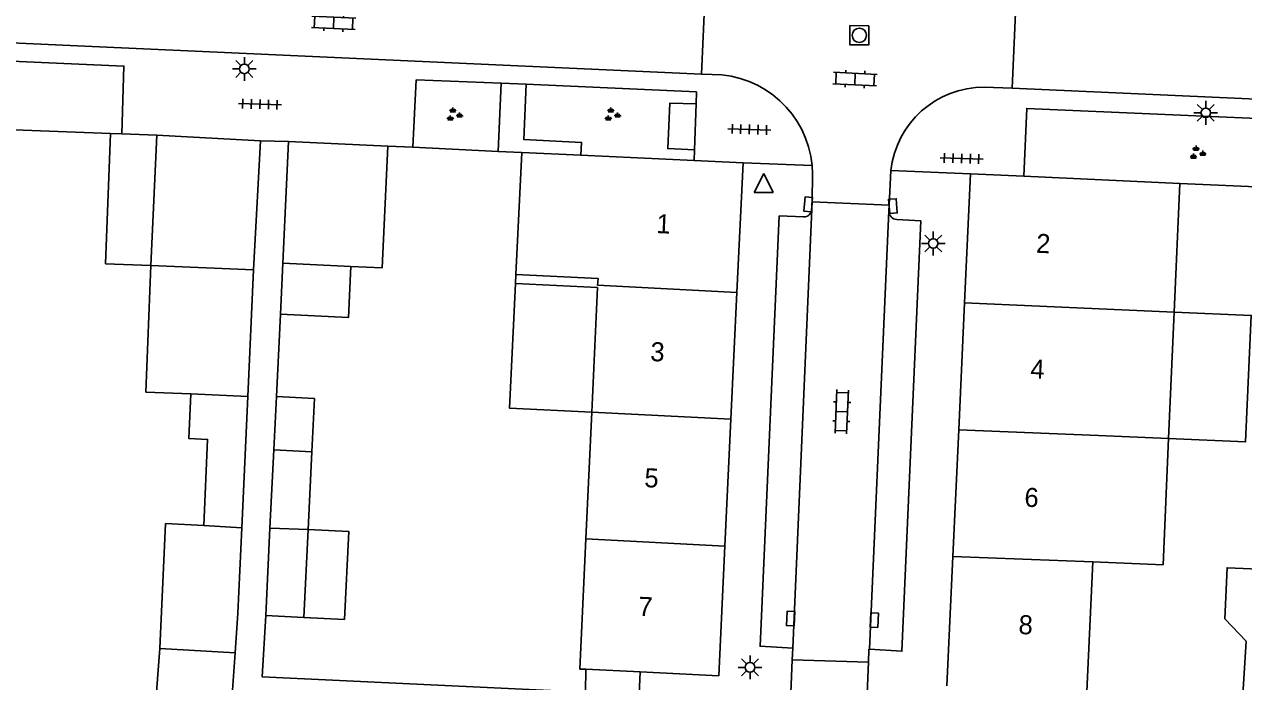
# Model space of a CAD drawing. Extents: x 132994 to 136000, y 393499 to 395512.
# Drawn here: x 133239.8 to 133303.8, y 395304.5 to 395339 of the extents above; entities that cross this region are included whole.
import ezdxf

# ---------------------------------------------------------------- set-up
doc = ezdxf.new("R2010")
doc.units = 0
for name, color, linetype in [('gg-afsc-erfafscheiding', 7, 'Continuous'), ('gg-afsc-muur', 7, 'Continuous'), ('gg-anno-huisnummerreeks BGT', 7, 'Continuous'), ('gg-bbg-bijgebouw', 7, 'Continuous'), ('gg-bbg-gedigitaliseerde bebouwing', 7, 'Continuous'), ('gg-bbg-gedigitaliseerde bijgebouw', 7, 'Continuous'), ('gg-bbg-hoofdgebouw', 7, 'Continuous'), ('gg-bbg-luifel en loopbrug', 7, 'Continuous'), ('gg-bbg-tussenscheiding', 7, 'Continuous'), ('gg-knt-verharding', 7, 'Continuous'), ('gg-knt-verharding nz', 7, 'Continuous'), ('gt-grn-weggrens', 7, 'Continuous'), ('gt-symb-groenvak', 7, 'Continuous'), ('gt-symb-klinker verharding', 7, 'Continuous'), ('gt-symb-kolk', 7, 'Continuous'), ('gt-symb-lichtmast', 7, 'Continuous'), ('gt-symb-rioolschacht', 7, 'Continuous'), ('gt-symb-tegel verharding', 7, 'Continuous'), ('gt-symb-waterafsluiter', 7, 'Continuous')]:
    doc.layers.add(name, color=color, linetype=linetype)

# ---------------------------------------------------------------- blocks, each defined once
blk = doc.blocks.new('gt0-LMAST')
at = {"layer": 'gt-symb-lichtmast'}
for p, q in [((-0.182, 0.173), (-0.447, 0.438)), ((-0.005, 0.246), (-0.005, 0.621)), ((0.172, 0.173), (0.437, 0.438)), ((-0.255, -0.004), (-0.63, -0.004)), ((-0.182, -0.181), (-0.447, -0.446)), ((-0.005, -0.254), (-0.005, -0.629)), ((0.437, -0.446), (0.172, -0.181)), ((0.245, -0.004), (0.62, -0.004))]:
    blk.add_line(p, q, dxfattribs=at)
blk.add_circle((-0.005, -0.004), 0.25, dxfattribs=at)
blk = doc.blocks.new('gt0-KL1')
at = {"layer": 'gt-symb-klinker verharding'}
for p, q in [((-1.15, 0.3), (1.15, 0.3)), ((-1, -0.3), (-1, 0.3)), ((-0.5, 0.3), (-0.5, 0.45)), ((0, -0.3), (0, 0.3)), ((0.5, 0.3), (0.5, 0.45)), ((1, -0.3), (1, 0.3)), ((-1.15, -0.3), (1.15, -0.3)), ((-0.5, -0.45), (-0.5, -0.3)), ((0.5, -0.45), (0.5, -0.3))]:
    blk.add_line(p, q, dxfattribs=at)
blk = doc.blocks.new('gt0-RS')
at = {"layer": 'gt-symb-rioolschacht'}
blk.add_lwpolyline([(-0.5, -0.5), (0.5, -0.5), (0.5, 0.5), (-0.5, 0.5)], close=True, dxfattribs=at)
blk.add_circle((0, 0), 0.375, dxfattribs=at)
blk = doc.blocks.new('gt0-GRVAK')
at = {"layer": 'gt-symb-groenvak'}
for p, q in [((-0.11, 0.189), (-0.228, 0.24)), ((-0.182, 0.153), (0.088, 0.153)), ((-0.091, 0.211), (-0.156, 0.322)), ((-0.047, 0.214), (-0.047, 0.393)), ((-0.004, 0.211), (0.061, 0.322)), ((0.015, 0.189), (0.133, 0.24)), ((0.262, -0.052), (0.197, 0.059)), ((0.305, -0.049), (0.305, 0.13)), ((0.349, -0.052), (0.414, 0.059)), ((-0.245, -0.228), (-0.363, -0.177)), ((-0.318, -0.264), (-0.047, -0.264)), ((-0.226, -0.206), (-0.291, -0.095)), ((-0.183, -0.203), (-0.183, -0.024)), ((-0.139, -0.206), (-0.074, -0.095)), ((-0.12, -0.228), (-0.002, -0.177)), ((0.243, -0.074), (0.125, -0.023)), ((0.17, -0.11), (0.441, -0.11)), ((0.368, -0.074), (0.486, -0.023))]:
    blk.add_line(p, q, dxfattribs=at)
blk = doc.blocks.new('gt0-TEG1')
at = {"layer": 'gt-symb-tegel verharding'}
for p, q in [((-1.125, 0), (1.125, 0)), ((-0.9, -0.25), (-0.9, 0.25)), ((-0.45, -0.25), (-0.45, 0.25)), ((0, -0.25), (0, 0.25)), ((0.45, -0.25), (0.45, 0.25)), ((0.9, -0.25), (0.9, 0.25))]:
    blk.add_line(p, q, dxfattribs=at)
blk = doc.blocks.new('gt0-KOLK')
at = {"layer": 'gt-symb-kolk'}
blk.add_lwpolyline([(0, 0), (0.375, 0), (0.375, 0.4), (-0.375, 0.4), (-0.375, 0), (0, 0)], dxfattribs=at)
blk = doc.blocks.new('gt0-WAFSL')
at = {"layer": 'gt-symb-waterafsluiter'}
for p, q in [((-0.5, -0.333), (0, 0.667)), ((0, 0.667), (0.5, -0.333)), ((0.5, -0.333), (-0.5, -0.333))]:
    blk.add_line(p, q, dxfattribs=at)

msp = doc.modelspace()

# ---------------------------------------------------------------- linework, layer by layer
at = {"layer": 'gg-afsc-erfafscheiding'}
for p, q in [((133253.018, 395319.465), (133253.229, 395323.795)), ((133252.268, 395304.753), (133252.458, 395307.972))]:
    msp.add_line(p, q, dxfattribs=at)
at = {"layer": 'gg-afsc-muur'}
for p, q in [((133238.29, 395333.515), (133244.32, 395333.283)), ((133260.176, 395332.557), (133258.871, 395332.619)), ((133264.663, 395332.346), (133260.176, 395332.557)), ((133265.893, 395332.288), (133264.663, 395332.346)), ((133300.438, 395330.663), (133306.752, 395330.372))]:
    msp.add_line(p, q, dxfattribs=at)
msp.add_lwpolyline([(133252.268, 395304.753), (133269.233, 395303.953), (133269.259, 395305.149)], dxfattribs=at)
at = {"layer": 'gg-bbg-bijgebouw'}
for p, q in [((133246.754, 395333.19), (133252.187, 395332.9)), ((133251.822, 395326.119), (133252.187, 395332.9)), ((133253.356, 395326.479), (133253.657, 395332.865)), ((133253.657, 395332.865), (133258.871, 395332.619)), ((133253.356, 395326.479), (133253.229, 395323.795))]:
    msp.add_line(p, q, dxfattribs=at)
at = {"layer": 'gg-bbg-gedigitaliseerde bebouwing'}
for p, q in [((133265.893, 395332.288), (133265.591, 395325.885)), ((133300.438, 395330.663), (133300.135, 395323.91)), ((133265.568, 395325.399), (133265.591, 395325.885)), ((133269.875, 395325.195), (133265.568, 395325.399)), ((133269.875, 395325.195), (133269.569, 395318.656)), ((133300.135, 395323.91), (133299.838, 395317.273)), ((133269.569, 395318.656), (133269.257, 395311.998)), ((133299.838, 395317.273), (133299.549, 395310.626)), ((133269.257, 395311.998), (133268.943, 395305.164)), ((133295.86, 395310.786), (133299.549, 395310.626))]:
    msp.add_line(p, q, dxfattribs=at)
at = {"layer": 'gg-bbg-gedigitaliseerde bijgebouw'}
for p, q in [((133246.754, 395333.19), (133246.431, 395326.35)), ((133251.822, 395326.119), (133251.525, 395319.473)), ((133251.525, 395319.473), (133251.212, 395312.586)), ((133252.682, 395312.565), (133252.882, 395316.672)), ((133252.882, 395316.672), (133254.879, 395316.574)), ((133254.879, 395316.574), (133254.68, 395312.497)), ((133252.458, 395307.972), (133252.682, 395312.565)), ((133254.68, 395312.497), (133254.454, 395307.874)), ((133254.454, 395307.874), (133252.458, 395307.972)), ((133246.904, 395306.234), (133246.384, 395299.643))]:
    msp.add_line(p, q, dxfattribs=at)
for points in [[(133256.932, 395326.302), (133258.569, 395326.225), (133258.871, 395332.619)], [(133246.431, 395326.35), (133246.176, 395319.705), (133248.537, 395319.614)], [(133253.229, 395323.795), (133256.805, 395323.626), (133256.932, 395326.302)], [(133248.537, 395319.614), (133248.427, 395317.265), (133249.406, 395317.219), (133249.215, 395312.692)], [(133246.904, 395306.234), (133247.209, 395312.8), (133249.215, 395312.692)], [(133251.212, 395312.586), (133250.995, 395308.101), (133250.849, 395306.014)], [(133309.162, 395310.211), (133302.911, 395310.481), (133302.791, 395307.806), (133303.92, 395306.621), (133303.65, 395302.41)], [(133250.849, 395306.014), (133250.695, 395303.816), (133250.463, 395299.429)]]:
    msp.add_lwpolyline(points, dxfattribs=at)
at = {"layer": 'gg-bbg-hoofdgebouw'}
for p, q in [((133269.002, 395332.141), (133265.893, 395332.288)), ((133274.942, 395331.861), (133269.002, 395332.141)), ((133277.51, 395331.74), (133274.942, 395331.861)), ((133277.189, 395324.932), (133277.51, 395331.74)), ((133289.138, 395324.397), (133289.45, 395331.17)), ((133289.45, 395331.17), (133292.237, 395331.041)), ((133292.237, 395331.041), (133300.438, 395330.663)), ((133276.875, 395318.275), (133277.189, 395324.932)), ((133288.83, 395317.724), (133289.138, 395324.397)), ((133276.561, 395311.617), (133276.875, 395318.275)), ((133288.523, 395311.077), (133288.83, 395317.724)), ((133276.24, 395304.81), (133276.561, 395311.617)), ((133288.21, 395304.28), (133288.523, 395311.077)), ((133295.547, 395303.976), (133295.86, 395310.786)), ((133269.259, 395305.149), (133268.943, 395305.164)), ((133272.11, 395305.011), (133269.259, 395305.149)), ((133276.24, 395304.81), (133272.11, 395305.011))]:
    msp.add_line(p, q, dxfattribs=at)
at = {"layer": 'gg-bbg-luifel en loopbrug'}
for p, q in [((133244.32, 395333.283), (133244.904, 395333.261)), ((133244.904, 395333.261), (133246.754, 395333.19)), ((133252.882, 395316.672), (133253.018, 395319.465))]:
    msp.add_line(p, q, dxfattribs=at)
for points in [[(133246.431, 395326.35), (133244.057, 395326.441), (133244.32, 395333.283)], [(133265.568, 395325.399), (133265.249, 395318.867), (133269.569, 395318.656)], [(133300.135, 395323.91), (133304.177, 395323.729), (133303.879, 395317.092), (133299.838, 395317.273)], [(133254.879, 395316.574), (133255.015, 395319.367), (133253.018, 395319.465)], [(133254.454, 395307.874), (133256.588, 395307.77), (133256.814, 395312.393), (133254.68, 395312.497)]]:
    msp.add_lwpolyline(points, dxfattribs=at)
at = {"layer": 'gg-bbg-tussenscheiding'}
for p, q in [((133246.431, 395326.35), (133251.822, 395326.119)), ((133256.932, 395326.302), (133253.356, 395326.479)), ((133269.877, 395325.314), (133277.189, 395324.932)), ((133289.138, 395324.397), (133300.135, 395323.91)), ((133251.525, 395319.473), (133248.537, 395319.614)), ((133269.569, 395318.656), (133276.875, 395318.275)), ((133288.83, 395317.724), (133296.161, 395317.433)), ((133296.161, 395317.433), (133299.838, 395317.273)), ((133251.212, 395312.586), (133249.215, 395312.692)), ((133254.68, 395312.497), (133252.682, 395312.565)), ((133269.257, 395311.998), (133276.561, 395311.617)), ((133288.523, 395311.077), (133295.86, 395310.786)), ((133246.904, 395306.234), (133250.849, 395306.014))]:
    msp.add_line(p, q, dxfattribs=at)
msp.add_lwpolyline([(133265.591, 395325.885), (133269.898, 395325.676), (133269.877, 395325.314)], dxfattribs=at)
at = {"layer": 'gg-knt-verharding'}
for p, q in [((133275.506, 395340.349), (133275.333, 395336.4)), ((133291.813, 395339.611), (133291.636, 395335.659)), ((133275.333, 395336.4), (133231.366, 395338.396)), ((133275.333, 395336.4), (133275.895, 395336.381)), ((133264.812, 395335.934), (133264.663, 395332.346)), ((133290.165, 395335.716), (133291.636, 395335.659)), ((133335.848, 395333.668), (133291.636, 395335.659)), ((133274.965, 395332.433), (133274.942, 395331.861)), ((133285.173, 395329.517), (133285.265, 395331.344)), ((133281.139, 395329.693), (133281.126, 395329.31)), ((133285.173, 395329.517), (133281.139, 395329.693)), ((133285.153, 395329.219), (133285.173, 395329.517)), ((133280.679, 395328.902), (133279.402, 395328.961)), ((133285.577, 395328.766), (133286.841, 395328.702)), ((133280.088, 395305.644), (133280.117, 395306.263)), ((133279.885, 395300.718), (133280.088, 395305.644)), ((133280.088, 395305.644), (133284.09, 395305.526)), ((133283.899, 395300.61), (133284.09, 395305.526))]:
    msp.add_line(p, q, dxfattribs=at)
for points in [[(133231.841, 395333.8), (133232.041, 395337.404), (133245.018, 395336.819), (133244.904, 395333.261)], [(133260.176, 395332.557), (133260.358, 395336.094), (133264.812, 395335.934)], [(133269.002, 395332.141), (133269.034, 395332.812), (133266.01, 395332.96), (133266.124, 395335.876)], [(133266.124, 395335.876), (133275.064, 395335.471), (133275.041, 395334.845)], [(133275.041, 395334.845), (133273.675, 395334.882), (133273.562, 395332.489), (133274.965, 395332.433)], [(133292.237, 395331.041), (133292.396, 395334.601), (133306.917, 395333.97)], [(133281.139, 395329.693), (133281.157, 395331.188), (133281.135, 395331.599)], [(133280.117, 395306.263), (133278.404, 395306.357), (133279.402, 395328.961)], [(133284.144, 395306.204), (133285.847, 395306.099), (133286.841, 395328.702)], [(133284.09, 395305.526), (133284.116, 395306.206), (133284.144, 395306.204)]]:
    msp.add_lwpolyline(points, dxfattribs=at)
for centre, radius, start, end in [((133275.886, 395331.11), 5.271, 5.32556, 89.90757), ((133290.16, 395330.789), 4.927, 89.94612, 173.53543), ((133280.688, 395329.341), 0.439, 268.85933, 355.91731), ((133285.601, 395329.213), 0.448, 179.22607, 266.98608)]:
    msp.add_arc(centre, radius, start, end, dxfattribs=at)
at = {"layer": 'gg-knt-verharding nz'}
for p, q in [((133281.126, 395329.31), (133280.117, 395306.263)), ((133285.153, 395329.219), (133284.144, 395306.204))]:
    msp.add_line(p, q, dxfattribs=at)
at = {"layer": 'gt-grn-weggrens'}
for p, q in [((133266.124, 395335.876), (133264.812, 395335.934)), ((133274.965, 395332.433), (133275.041, 395334.845)), ((133253.657, 395332.865), (133252.187, 395332.9)), ((133277.51, 395331.74), (133281.135, 395331.599)), ((133285.265, 395331.344), (133289.45, 395331.17)), ((133271.94, 395301.1), (133272.11, 395305.011))]:
    msp.add_line(p, q, dxfattribs=at)

# ---------------------------------------------------------------- block references
at = {"layer": 'gt-symb-groenvak'}
for p in [(133262.329, 395334.26), (133270.62, 395334.26), (133301.33, 395332.252)]:
    msp.add_blockref('gt0-GRVAK', p, dxfattribs=at)
at = {"layer": 'gt-symb-klinker verharding'}
for p, rotation in [((133256.023, 395339.092), -2.6936110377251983), ((133283.386, 395336.142), -2.6936110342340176), ((133282.687, 395318.675), -92.57914750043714)]:
    msp.add_blockref('gt0-KL1', p, dxfattribs=dict(at, rotation=rotation))
at = {"layer": 'gt-symb-kolk'}
for p, rotation in [((133281.126, 395329.549), 84.95083353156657), ((133285.178, 395329.454), -85.75513794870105), ((133280.203, 395307.804), 87.59258615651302), ((133284.193, 395307.74), -92.52190794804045)]:
    msp.add_blockref('gt0-KOLK', p, dxfattribs=dict(at, rotation=rotation))
at = {"layer": 'gt-symb-lichtmast'}
for p in [(133251.345, 395336.678), (133301.795, 395334.375), (133287.497, 395327.514), (133277.88, 395305.256)]:
    msp.add_blockref('gt0-LMAST', p, dxfattribs=at)
at = {"layer": 'gt-symb-rioolschacht', "rotation": 179.25519682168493}
msp.add_blockref('gt0-RS', (133283.612, 395338.44), dxfattribs=at)
at = {"layer": 'gt-symb-tegel verharding'}
for p, rotation in [((133252.157, 395334.82), -1.8346729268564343), ((133277.841, 395333.498), -1.8346729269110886), ((133288.979, 395331.972), -1.8346729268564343)]:
    msp.add_blockref('gt0-TEG1', p, dxfattribs=dict(at, rotation=rotation))
at = {"layer": 'gt-symb-waterafsluiter'}
msp.add_blockref('gt0-WAFSL', (133278.593, 395330.512), dxfattribs=at)

# ---------------------------------------------------------------- texts
at = {"layer": 'gg-anno-huisnummerreeks BGT'}
for s, rotation, p in [('1', 357.3, (133272.944, 395328.058)), ('2', 357.4, (133292.874, 395327.024)), ('3', 357.3, (133272.627, 395321.339)), ('4', 357.4, (133292.57, 395320.433)), ('5', 357.3, (133272.314, 395314.717)), ('6', 357.4, (133292.259, 395313.692)), ('7', 357.3, (133271.996, 395307.964)), ('8', 357.4, (133291.951, 395307.006))]:
    msp.add_text(s, height=1, rotation=rotation, dxfattribs=at).set_placement(p)

doc.saveas('drawing.dxf')
